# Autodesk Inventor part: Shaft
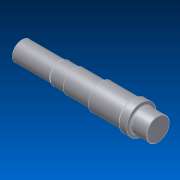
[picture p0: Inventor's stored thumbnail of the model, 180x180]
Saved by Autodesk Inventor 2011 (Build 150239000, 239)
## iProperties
Created: 2011-05
Part Number: Shaft
Material: Steel
Document SubType Name: Modeling
Designer: 904Chiaki
Density: 7.85 g/cm^3
Mass: 12704.9 g
Surface Area: 1051.05 cm^2
Volume: 1618.46 cm^3
CustomPartVersion: 1
Author: 904Chiaki
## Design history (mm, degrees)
sketch "Main Sketch"
  geometry: L1 (0, 0)-(416, 0) reference; L2 (0, 0)-(0, 30); L3 (0, 30)-(120, 30); L4 (120, 30)-(120, 32.5); L5 (120, 32.5)-(160, 32.5); L6 (160, 32.5)-(160, 35); L7 (160, 35)-(242, 35); L8 (242, 35)-(242, 40); L9 (242, 40)-(342, 40); L10 (342, 40)-(342, 45); L11 (365, 45)-(365, 35); L12 (342, 45)-(365, 45); L13 (416, 35)-(416, 0); L14 (365, 35)-(416, 35)
  constraints: 28 end point, 7 vertical, 3 horizontal
  dimensions: "d3" = 60 diameter of L3 L1 (derived); "d4" = 65 diameter of L5 L1 (derived); "d5" = 70 diameter of L7 L1 (derived); "d6" = 80 diameter of L9 L1 (derived); "d7" = 90 diameter of L12 L1 (derived); "d8" = 70 diameter of L14 L1 (derived)
revolve "Revolution1" sketch "Main Sketch" stored, may be unused: angle "d9" = 0 deg
node "Keyway2"
chamfer "Chamfer13" distance "d46" = 1; stored, may be unused: second distance "d47" = 0.125, angle "d48" = 45 deg
node "Keyway1"
node "Relief2"
node "Relief3"
node "Relief4"
chamfer "Chamfer5" distance "d22" = 1; stored, may be unused: second distance "d23" = 0.125, angle "d24" = 45 deg
workpoint "Work Point1"
hole "Hole1" diameter "d51" = 14; stored, may be unused: countersink angle "d55" = 90 deg, drill point angle "d57" = 118 deg; dims "d49" = 10, "d50" = 10, "d52" = 6, "d53" = 4, "d54" = 2, "d56" = 60
chamfer "Chamfer14" distance "d58" = 1; stored, may be unused: second distance "d59" = 2, angle "d60" = 45 deg
thread "Thread1" dims "d61" = 10, "d62" = 0
body "Solid1"
feature "iFeature1:2"
feature "iFeature1:3"
feature "iFeature1:4"
chamfer "Chamfer6" distance "d25" = 1; stored, may be unused: second distance "d26" = 1, angle "d27" = 45 deg
feature "iFeature1:5"
feature "iFeature3:1"
other parameters: "d0" = 0, "d1" = 0, "d2" = 0
